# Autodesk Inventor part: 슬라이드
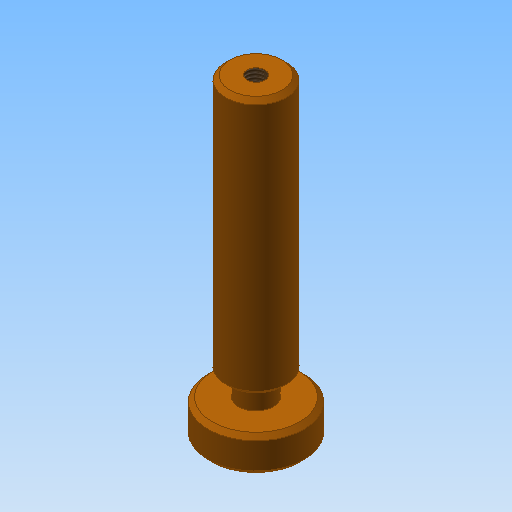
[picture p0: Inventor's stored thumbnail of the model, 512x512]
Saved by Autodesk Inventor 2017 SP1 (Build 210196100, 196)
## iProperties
Created: 2015-09
Part Number: 슬라이드
Material: 강철, 연강
Document SubType Name: Modeling
Designer: mduedu
Density: 1 g/cm^3
Appearance: 주황색
Author: mduedu
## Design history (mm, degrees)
sketch "스케치1"
  geometry: C1 r 11 at (0, 0); 1 further point
  constraints: 1 centre point, 1 coincident
  dimensions: "d0" = 22 diameter of C1
extrude "돌출1" new body sketch "스케치1" distance "d1" = 8; taper "d2" = 0 deg
sketch "스케치2"
  geometry: C1 r 4 at (0, 0); 1 further point
  constraints: 1 centre point, 1 coincident
  dimensions: "d3" = 8 diameter of C1
extrude "돌출2" join sketch "스케치2" distance "d4" = 5; taper "d5" = 0 deg
sketch "스케치3"
  geometry: C1 r 7 at (0, 0); 1 further point
  constraints: 1 centre point, 1 coincident
  dimensions: "d6" = 14 diameter of C1
extrude "돌출3" join sketch "스케치3" distance "d7" = 59; taper "d8" = 0 deg
hole "구멍1" diameter "d11" = 4.134; stored, may be unused: countersink angle "d15" = 90 deg, drill point angle "d17" = 118 deg; dims "d9" = 10, "d10" = 10, "d12" = 9, "d13" = 4, "d14" = 2, "d16" = 12
chamfer "모따기1" distance "d18" = 1; stored, may be unused: second distance "d19" = 2, angle "d20" = 45 deg
node "솔리드1"
